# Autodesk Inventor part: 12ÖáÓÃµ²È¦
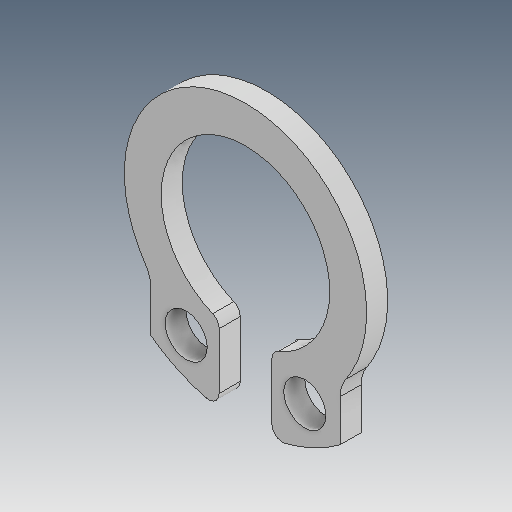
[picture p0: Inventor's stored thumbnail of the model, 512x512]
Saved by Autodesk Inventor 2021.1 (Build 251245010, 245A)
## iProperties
Created: 2019-05
Part Number: 12ÖáÓÃµ²È¦
Material: Ogólny
Document SubType Name: Modeling
Designer: user
Density: 1 g/cm^3
Appearance: Domyślna
Author: user
Revision Number: ÈÎºÎ
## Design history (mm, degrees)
feature "ÊäÈë1"
node "Bryła1"
